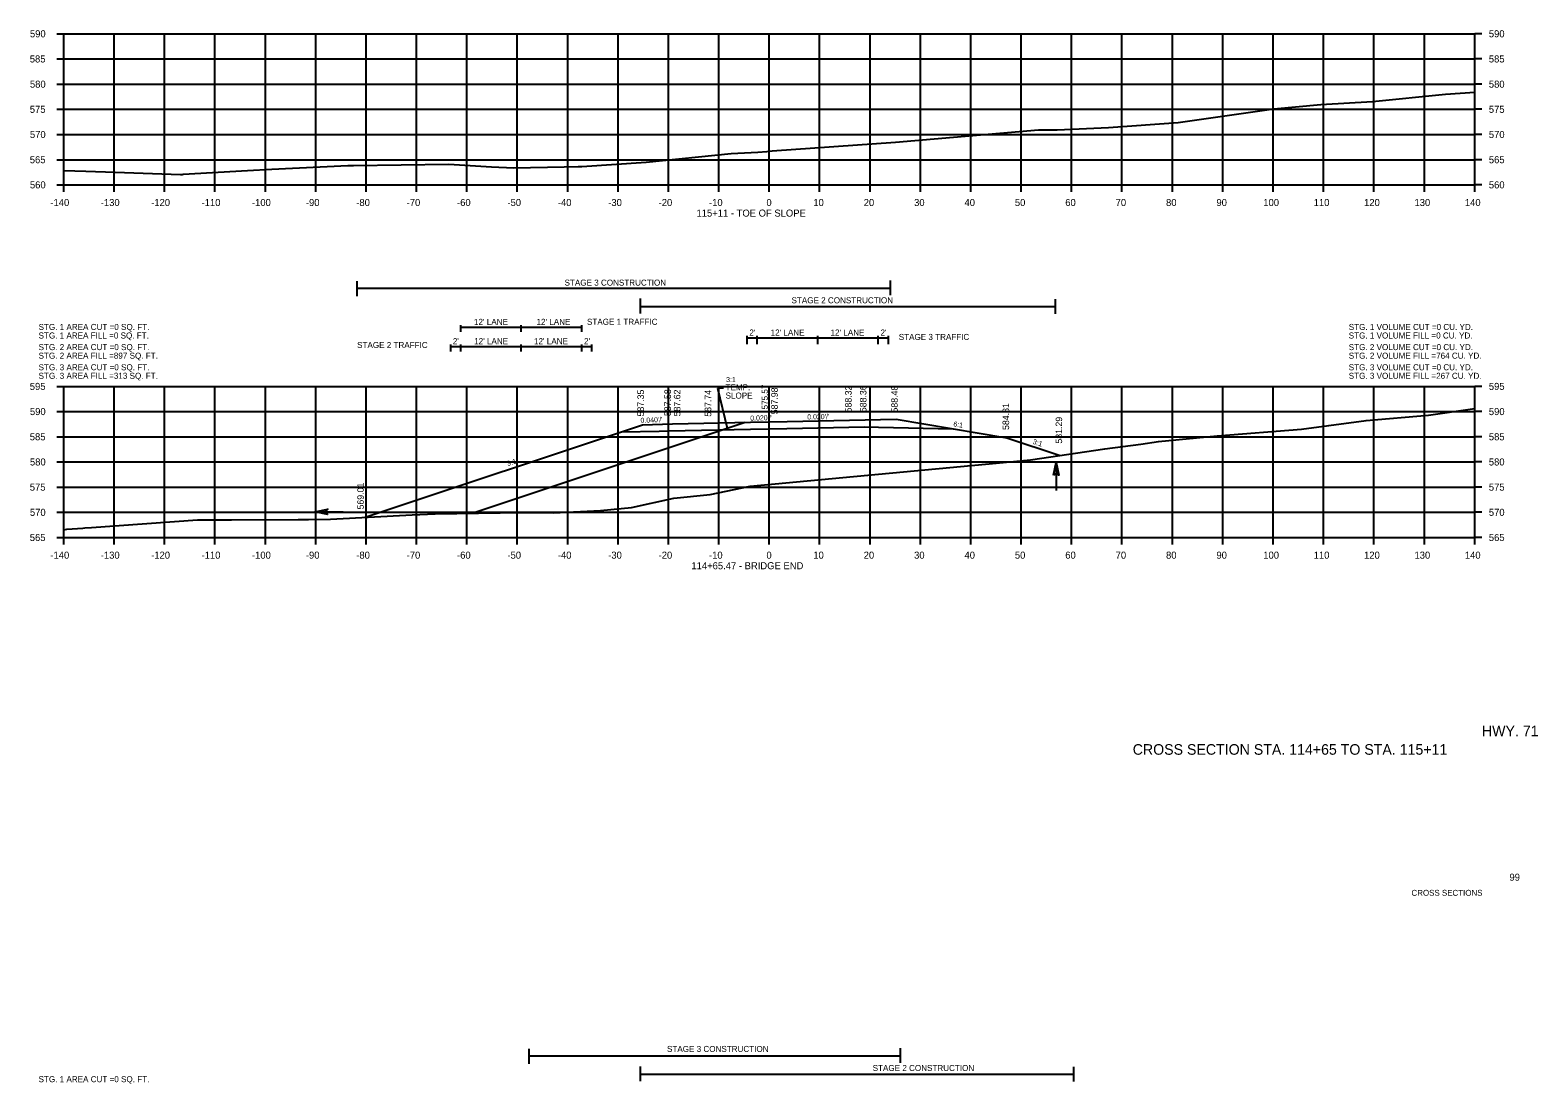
# Model space of a CAD drawing. Extents: x 642114 to 642416, y 286928 to 293347.
# Drawn here: x 642113.6 to 642412.8, y 289750.7 to 289959.9 of the extents above; entities that cross this region are included whole.
import ezdxf

# ---------------------------------------------------------------- set-up
doc = ezdxf.new("R2010")
doc.units = 0
for name, color, linetype in [('59', 7, 'Continuous'), ('Level 43', 7, 'Continuous'), ('Level 58', 7, 'Continuous'), ('R_Axis', 7, 'Continuous'), ('R_Axis Annot', 7, 'Continuous'), ('R_Border', 7, 'Continuous'), ('R_Border Notes', 7, 'Continuous'), ('R_Draft', 7, 'Continuous'), ('R_Exist Surface', 7, 'Continuous'), ('R_Exist Surface Annot', 7, 'Continuous'), ('R_Fin Surface', 7, 'Continuous'), ('R_Grid', 7, 'Continuous'), ('R_Xsect Elev', 7, 'Continuous'), ('R_Xsect Slope', 7, 'Continuous')]:
    doc.layers.add(name, color=color, linetype=linetype)

# ---------------------------------------------------------------- blocks, each defined once
blk = doc.blocks.new('FA')
at = {"layer": 'Level 43'}
blk.add_lwpolyline([(7.94, 0), (0, 0)], dxfattribs=at)
at = {"layer": 'Level 58'}
blk.add_lwpolyline([(4.34, 0.75), (7.94, 0), (4.34, -0.75), (4.94, 0)], close=True, dxfattribs=at)

msp = doc.modelspace()

# ---------------------------------------------------------------- linework, layer by layer
at = {"layer": 'R_Axis'}
for p, q in [((642118.84, 289959.14), (642120.24, 289959.14)), ((642120.24, 289929.14), (642120.24, 289959.14)), ((642400.24, 289929.14), (642400.24, 289959.14)), ((642401.64, 289959.14), (642400.24, 289959.14)), ((642118.84, 289954.14), (642120.24, 289954.14)), ((642401.64, 289954.14), (642400.24, 289954.14)), ((642118.84, 289949.14), (642120.24, 289949.14)), ((642401.64, 289949.14), (642400.24, 289949.14)), ((642118.84, 289944.14), (642120.24, 289944.14)), ((642401.64, 289944.14), (642400.24, 289944.14)), ((642118.84, 289939.14), (642120.24, 289939.14)), ((642401.64, 289939.14), (642400.24, 289939.14)), ((642118.84, 289934.14), (642120.24, 289934.14)), ((642401.64, 289934.14), (642400.24, 289934.14)), ((642118.84, 289929.14), (642120.24, 289929.14)), ((642120.24, 289929.14), (642400.24, 289929.14)), ((642120.24, 289927.74), (642120.24, 289929.14)), ((642130.24, 289927.74), (642130.24, 289929.14)), ((642140.24, 289927.74), (642140.24, 289929.14)), ((642150.24, 289927.74), (642150.24, 289929.14)), ((642160.24, 289927.74), (642160.24, 289929.14)), ((642170.24, 289927.74), (642170.24, 289929.14)), ((642180.24, 289927.74), (642180.24, 289929.14)), ((642190.24, 289927.74), (642190.24, 289929.14)), ((642200.24, 289927.74), (642200.24, 289929.14)), ((642210.24, 289927.74), (642210.24, 289929.14)), ((642220.24, 289927.74), (642220.24, 289929.14)), ((642230.24, 289927.74), (642230.24, 289929.14)), ((642240.24, 289927.74), (642240.24, 289929.14)), ((642250.24, 289927.74), (642250.24, 289929.14)), ((642260.24, 289927.74), (642260.24, 289929.14)), ((642270.24, 289927.74), (642270.24, 289929.14)), ((642280.24, 289927.74), (642280.24, 289929.14)), ((642290.24, 289927.74), (642290.24, 289929.14)), ((642300.24, 289927.74), (642300.24, 289929.14)), ((642310.24, 289927.74), (642310.24, 289929.14)), ((642320.24, 289927.74), (642320.24, 289929.14)), ((642330.24, 289927.74), (642330.24, 289929.14)), ((642340.24, 289927.74), (642340.24, 289929.14)), ((642350.24, 289927.74), (642350.24, 289929.14)), ((642360.24, 289927.74), (642360.24, 289929.14)), ((642370.24, 289927.74), (642370.24, 289929.14)), ((642380.24, 289927.74), (642380.24, 289929.14)), ((642390.24, 289927.74), (642390.24, 289929.14)), ((642400.24, 289927.74), (642400.24, 289929.14)), ((642401.64, 289929.14), (642400.24, 289929.14)), ((642118.84, 289889.14), (642120.24, 289889.14)), ((642120.24, 289859.14), (642120.24, 289889.14)), ((642400.24, 289859.14), (642400.24, 289889.14)), ((642401.64, 289889.14), (642400.24, 289889.14)), ((642118.84, 289884.14), (642120.24, 289884.14)), ((642401.64, 289884.14), (642400.24, 289884.14)), ((642118.84, 289879.14), (642120.24, 289879.14)), ((642401.64, 289879.14), (642400.24, 289879.14)), ((642118.84, 289874.14), (642120.24, 289874.14)), ((642401.64, 289874.14), (642400.24, 289874.14)), ((642118.84, 289869.14), (642120.24, 289869.14)), ((642401.64, 289869.14), (642400.24, 289869.14)), ((642118.84, 289864.14), (642120.24, 289864.14)), ((642401.64, 289864.14), (642400.24, 289864.14)), ((642118.84, 289859.14), (642120.24, 289859.14)), ((642120.24, 289859.14), (642400.24, 289859.14)), ((642120.24, 289857.74), (642120.24, 289859.14)), ((642130.24, 289857.74), (642130.24, 289859.14)), ((642140.24, 289857.74), (642140.24, 289859.14)), ((642150.24, 289857.74), (642150.24, 289859.14)), ((642160.24, 289857.74), (642160.24, 289859.14)), ((642170.24, 289857.74), (642170.24, 289859.14)), ((642180.24, 289857.74), (642180.24, 289859.14)), ((642190.24, 289857.74), (642190.24, 289859.14)), ((642200.24, 289857.74), (642200.24, 289859.14)), ((642210.24, 289857.74), (642210.24, 289859.14)), ((642220.24, 289857.74), (642220.24, 289859.14)), ((642230.24, 289857.74), (642230.24, 289859.14)), ((642240.24, 289857.74), (642240.24, 289859.14)), ((642250.24, 289857.74), (642250.24, 289859.14)), ((642260.24, 289857.74), (642260.24, 289859.14)), ((642270.24, 289857.74), (642270.24, 289859.14)), ((642280.24, 289857.74), (642280.24, 289859.14)), ((642290.24, 289857.74), (642290.24, 289859.14)), ((642300.24, 289857.74), (642300.24, 289859.14)), ((642310.24, 289857.74), (642310.24, 289859.14)), ((642320.24, 289857.74), (642320.24, 289859.14)), ((642330.24, 289857.74), (642330.24, 289859.14)), ((642340.24, 289857.74), (642340.24, 289859.14)), ((642350.24, 289857.74), (642350.24, 289859.14)), ((642360.24, 289857.74), (642360.24, 289859.14)), ((642370.24, 289857.74), (642370.24, 289859.14)), ((642380.24, 289857.74), (642380.24, 289859.14)), ((642390.24, 289857.74), (642390.24, 289859.14)), ((642400.24, 289857.74), (642400.24, 289859.14)), ((642401.64, 289859.14), (642400.24, 289859.14))]:
    msp.add_line(p, q, dxfattribs=at)
at = {"layer": 'R_Exist Surface'}
for points in [[(642120.24, 289932.01), (642124.59, 289931.86), (642130.41, 289931.67), (642143.38, 289931.22), (642143.71, 289931.23), (642143.92, 289931.25), (642156.69, 289931.99), (642161.54, 289932.27), (642176.58, 289932.97), (642177.51, 289932.99), (642177.71, 289932.98), (642196.67, 289933.22), (642205.09, 289932.74), (642209.52, 289932.51), (642219.55, 289932.73), (642222.32, 289932.78), (642222.94, 289932.77), (642223.06, 289932.8), (642235.81, 289933.67), (642252.65, 289935.38), (642257.97, 289935.64), (642259.75, 289935.78), (642260.82, 289935.87), (642285.28, 289937.62), (642313.64, 289940.07), (642317.36, 289940.06), (642327.59, 289940.53), (642341.41, 289941.51), (642360.37, 289944.23), (642369.67, 289945.09), (642379.93, 289945.7), (642394.43, 289947.17), (642400.24, 289947.55)], [(642230.94, 289880.12), (642238.42, 289880.27), (642240.33, 289880.3), (642256.49, 289880.63), (642260.24, 289880.7), (642263.76, 289880.77), (642279.13, 289881.08), (642281.92, 289881.02), (642296.76, 289880.73)]]:
    msp.add_lwpolyline(points, dxfattribs=at)
at = {"layer": 'R_Exist Surface Annot'}
msp.add_lwpolyline([(642120.24, 289860.69), (642120.86, 289860.77), (642124.01, 289860.99), (642124.41, 289861.03), (642125.75, 289861.13), (642146.78, 289862.68), (642153.5, 289862.62), (642166.78, 289862.74), (642168.81, 289862.73), (642173.18, 289862.79), (642189.36, 289863.63), (642193.92, 289863.86), (642211.16, 289864.11), (642217.39, 289864.04), (642226.74, 289864.53), (642232.91, 289865.09), (642241.32, 289866.98), (642248.52, 289867.7), (642256.43, 289869.35), (642305.26, 289873.91), (642312.07, 289874.53), (642326.83, 289876.76), (642333.96, 289877.69), (642337.46, 289878.17), (642349.11, 289879.32), (642365.87, 289880.64), (642371.3, 289881.37), (642378.71, 289882.36), (642391.07, 289883.41), (642400.24, 289884.77)], dxfattribs=at)
at = {"layer": 'R_Fin Surface'}
for points in [[(642180.02, 289863.15), (642235.07, 289881.49), (642241.07, 289881.73), (642256.49, 289882.04), (642260.24, 289882.12), (642263.77, 289882.19), (642285.41, 289882.62)], [(642285.41, 289882.62), (642307.41, 289878.95), (642317.99, 289875.42)]]:
    msp.add_lwpolyline(points, dxfattribs=at)
at = {"layer": 'R_Grid'}
for p, q in [((642120.24, 289959.14), (642400.24, 289959.14)), ((642120.24, 289929.14), (642120.24, 289959.14)), ((642130.24, 289929.14), (642130.24, 289959.14)), ((642140.24, 289929.14), (642140.24, 289959.14)), ((642150.24, 289929.14), (642150.24, 289959.14)), ((642160.24, 289929.14), (642160.24, 289959.14)), ((642170.24, 289929.14), (642170.24, 289959.14)), ((642180.24, 289929.14), (642180.24, 289959.14)), ((642190.24, 289929.14), (642190.24, 289959.14)), ((642200.24, 289929.14), (642200.24, 289959.14)), ((642210.24, 289929.14), (642210.24, 289959.14)), ((642220.24, 289929.14), (642220.24, 289959.14)), ((642230.24, 289929.14), (642230.24, 289959.14)), ((642240.24, 289929.14), (642240.24, 289959.14)), ((642250.24, 289929.14), (642250.24, 289959.14)), ((642260.24, 289929.14), (642260.24, 289959.14)), ((642270.24, 289929.14), (642270.24, 289959.14)), ((642280.24, 289929.14), (642280.24, 289959.14)), ((642290.24, 289929.14), (642290.24, 289959.14)), ((642300.24, 289929.14), (642300.24, 289959.14)), ((642310.24, 289929.14), (642310.24, 289959.14)), ((642320.24, 289929.14), (642320.24, 289959.14)), ((642330.24, 289929.14), (642330.24, 289959.14)), ((642340.24, 289929.14), (642340.24, 289959.14)), ((642350.24, 289929.14), (642350.24, 289959.14)), ((642360.24, 289929.14), (642360.24, 289959.14)), ((642370.24, 289929.14), (642370.24, 289959.14)), ((642380.24, 289929.14), (642380.24, 289959.14)), ((642390.24, 289929.14), (642390.24, 289959.14)), ((642400.24, 289929.14), (642400.24, 289959.14)), ((642120.24, 289954.14), (642400.24, 289954.14)), ((642120.24, 289949.14), (642400.24, 289949.14)), ((642120.24, 289944.14), (642400.24, 289944.14)), ((642120.24, 289939.14), (642400.24, 289939.14)), ((642120.24, 289934.14), (642400.24, 289934.14)), ((642120.24, 289929.14), (642400.24, 289929.14)), ((642120.24, 289889.14), (642400.24, 289889.14)), ((642120.24, 289859.14), (642120.24, 289889.14)), ((642130.24, 289859.14), (642130.24, 289889.14)), ((642140.24, 289859.14), (642140.24, 289889.14)), ((642150.24, 289859.14), (642150.24, 289889.14)), ((642160.24, 289859.14), (642160.24, 289889.14)), ((642170.24, 289859.14), (642170.24, 289889.14)), ((642180.24, 289859.14), (642180.24, 289889.14)), ((642190.24, 289859.14), (642190.24, 289889.14)), ((642200.24, 289859.14), (642200.24, 289889.14)), ((642210.24, 289859.14), (642210.24, 289889.14)), ((642220.24, 289859.14), (642220.24, 289889.14)), ((642230.24, 289859.14), (642230.24, 289889.14)), ((642240.24, 289859.14), (642240.24, 289889.14)), ((642250.24, 289859.14), (642250.24, 289889.14)), ((642260.24, 289859.14), (642260.24, 289889.14)), ((642270.24, 289859.14), (642270.24, 289889.14)), ((642280.24, 289859.14), (642280.24, 289889.14)), ((642290.24, 289859.14), (642290.24, 289889.14)), ((642300.24, 289859.14), (642300.24, 289889.14)), ((642310.24, 289859.14), (642310.24, 289889.14)), ((642320.24, 289859.14), (642320.24, 289889.14)), ((642330.24, 289859.14), (642330.24, 289889.14)), ((642340.24, 289859.14), (642340.24, 289889.14)), ((642350.24, 289859.14), (642350.24, 289889.14)), ((642360.24, 289859.14), (642360.24, 289889.14)), ((642370.24, 289859.14), (642370.24, 289889.14)), ((642380.24, 289859.14), (642380.24, 289889.14)), ((642390.24, 289859.14), (642390.24, 289889.14)), ((642400.24, 289859.14), (642400.24, 289889.14)), ((642120.24, 289884.14), (642400.24, 289884.14)), ((642120.24, 289879.14), (642400.24, 289879.14)), ((642120.24, 289874.14), (642400.24, 289874.14)), ((642120.24, 289869.14), (642400.24, 289869.14)), ((642120.24, 289864.14), (642400.24, 289864.14)), ((642120.24, 289859.14), (642400.24, 289859.14))]:
    msp.add_line(p, q, dxfattribs=at)
at = {"layer": 'R_Xsect Elev'}
for p, q in [((642178.45, 289907.08), (642178.45, 289910.01)), ((642284.28, 289907.22), (642284.28, 289910.15)), ((642178.45, 289908.66), (642284.28, 289908.66)), ((642234.67, 289903.63), (642234.67, 289906.56)), ((642317.06, 289903.54), (642317.06, 289906.47)), ((642234.67, 289905.01), (642317.06, 289905.01)), ((642199.03, 289899.99), (642199.03, 289901.31)), ((642199.03, 289900.89), (642223.03, 289900.89)), ((642211.03, 289899.99), (642211.03, 289901.31)), ((642223.03, 289899.99), (642223.03, 289901.31)), ((642197.03, 289896.04), (642197.03, 289897.47)), ((642197.03, 289897.06), (642225.03, 289897.06)), ((642199.03, 289896.04), (642199.03, 289897.47)), ((642211.03, 289896.04), (642211.03, 289897.47)), ((642223.03, 289896.04), (642223.03, 289897.47)), ((642225.03, 289896.04), (642225.03, 289897.47)), ((642255.87, 289897.53), (642255.87, 289899.19)), ((642255.87, 289898.77), (642283.87, 289898.77)), ((642257.87, 289897.53), (642257.87, 289899.19)), ((642269.87, 289897.53), (642269.87, 289899.19)), ((642281.87, 289897.53), (642281.87, 289899.19)), ((642283.87, 289897.53), (642283.87, 289899.19)), ((642201.28, 289863.96), (642255.46, 289882.02)), ((642212.57, 289754.69), (642212.57, 289757.61)), ((642286.31, 289754.83), (642286.31, 289757.75)), ((642212.57, 289756.26), (642286.31, 289756.26)), ((642234.67, 289751.24), (642234.67, 289754.16)), ((642320.71, 289751.14), (642320.71, 289754.07)), ((642234.67, 289752.62), (642320.71, 289752.62))]:
    msp.add_line(p, q, dxfattribs=at)
for points in [[(642251.17, 289888.82), (642249.95, 289888.82)], [(642249.95, 289888.82), (642251.91, 289880.87)]]:
    msp.add_lwpolyline(points, dxfattribs=at)

# ---------------------------------------------------------------- block references
at = {"layer": 'R_Xsect Elev', "xscale": 0.7, "yscale": 0.7}
for p, rotation in [((642317.2, 289868.46), 89.99999999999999), ((642175.65, 289864.23), 179.99999999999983)]:
    msp.add_blockref('FA', p, dxfattribs=dict(at, rotation=rotation))

# ---------------------------------------------------------------- texts
at = {"layer": '59'}
for s, p in [(' 587.35', (642235.38, 289882.69)), (' 587.58', (642240.73, 289882.77)), (' 587.62', (642242.61, 289882.71)), (' 587.74', (642248.73, 289882.64)), (' 587.98', (642261.94, 289883.12)), (' 588.32', (642276.58, 289883.5)), (' 588.36', (642279.53, 289883.54)), (' 588.48', (642285.74, 289883.47)), (' 584.81', (642307.84, 289880.01)), (' 581.29', (642318.36, 289877.3)), (' 569.01', (642179.78, 289864.22))]:
    msp.add_text(s, height=1.3, rotation=90, dxfattribs=at).set_placement(p)
at = {"layer": 'R_Axis Annot'}
for s, height, p in [('590', 1.4, (642113.52, 289958.44)), ('590', 1.4, (642403.04, 289958.44)), ('585', 1.4, (642113.49, 289953.44)), ('585', 1.4, (642403.04, 289953.44)), ('580', 1.4, (642113.52, 289948.44)), ('580', 1.4, (642403.04, 289948.44)), ('575', 1.4, (642113.49, 289943.44)), ('575', 1.4, (642403.04, 289943.44)), ('570', 1.4, (642113.52, 289938.44)), ('570', 1.4, (642403.04, 289938.44)), ('565', 1.4, (642113.49, 289933.44)), ('565', 1.4, (642403.04, 289933.44)), ('560', 1.4, (642113.52, 289928.44)), ('560', 1.4, (642403.04, 289928.44)), ('-140', 1.4, (642117.58, 289924.94)), ('-130', 1.4, (642127.58, 289924.94)), ('-120', 1.4, (642137.58, 289924.94)), ('-110', 1.4, (642147.58, 289924.94)), ('-100', 1.4, (642157.58, 289924.94)), ('-90', 1.4, (642168.28, 289924.94)), ('-80', 1.4, (642178.28, 289924.94)), ('-70', 1.4, (642188.28, 289924.94)), ('-60', 1.4, (642198.28, 289924.94)), ('-50', 1.4, (642208.28, 289924.94)), ('-40', 1.4, (642218.28, 289924.94)), ('-30', 1.4, (642228.28, 289924.94)), ('-20', 1.4, (642238.28, 289924.94)), ('115+11 - TOE OF SLOPE', 1.4, (642245.8, 289922.84)), ('-10', 1.4, (642248.28, 289924.94)), ('0', 1.4, (642259.68, 289924.94)), ('10', 1.4, (642268.98, 289924.94)), ('20', 1.4, (642278.98, 289924.94)), ('30', 1.4, (642288.98, 289924.94)), ('40', 1.4, (642298.98, 289924.94)), ('50', 1.4, (642308.98, 289924.94)), ('60', 1.4, (642318.98, 289924.94)), ('70', 1.4, (642328.98, 289924.94)), ('80', 1.4, (642338.98, 289924.94)), ('90', 1.4, (642348.98, 289924.94)), ('100', 1.4, (642358.28, 289924.94)), ('110', 1.4, (642368.28, 289924.94)), ('120', 1.4, (642378.28, 289924.94)), ('130', 1.4, (642388.28, 289924.94)), ('140', 1.4, (642398.28, 289924.94)), ('595', 1.4, (642113.49, 289888.44)), ('595', 1.4, (642403.04, 289888.44)), ('590', 1.4, (642113.52, 289883.44)), ('590', 1.4, (642403.04, 289883.44)), ('585', 1.4, (642113.49, 289878.44)), ('585', 1.4, (642403.04, 289878.44)), ('580', 1.4, (642113.52, 289873.44)), ('580', 1.4, (642403.04, 289873.44)), ('575', 1.4, (642113.49, 289868.44)), ('575', 1.4, (642403.04, 289868.44)), ('570', 1.4, (642113.52, 289863.44)), ('570', 1.4, (642403.04, 289863.44)), ('565', 1.4, (642113.49, 289858.44)), ('565', 1.4, (642403.04, 289858.44)), ('-140', 1.4, (642117.58, 289854.94)), ('-130', 1.4, (642127.58, 289854.94)), ('-120', 1.4, (642137.58, 289854.94)), ('-110', 1.4, (642147.58, 289854.94)), ('-100', 1.4, (642157.58, 289854.94)), ('-90', 1.4, (642168.28, 289854.94)), ('-80', 1.4, (642178.28, 289854.94)), ('-70', 1.4, (642188.28, 289854.94)), ('-60', 1.4, (642198.28, 289854.94)), ('-50', 1.4, (642208.28, 289854.94)), ('-40', 1.4, (642218.28, 289854.94)), ('-30', 1.4, (642228.28, 289854.94)), ('-20', 1.4, (642238.28, 289854.94)), ('-10', 1.4, (642248.28, 289854.94)), ('0', 1.4, (642259.68, 289854.94)), ('10', 1.4, (642268.98, 289854.94)), ('20', 1.4, (642278.98, 289854.94)), ('30', 1.4, (642288.98, 289854.94)), ('40', 1.4, (642298.98, 289854.94)), ('50', 1.4, (642308.98, 289854.94)), ('60', 1.4, (642318.98, 289854.94)), ('70', 1.4, (642328.98, 289854.94)), ('80', 1.4, (642338.98, 289854.94)), ('90', 1.4, (642348.98, 289854.94)), ('100', 1.4, (642358.28, 289854.94)), ('110', 1.4, (642368.28, 289854.94)), ('120', 1.4, (642378.28, 289854.94)), ('130', 1.4, (642388.28, 289854.94)), ('140', 1.4, (642398.28, 289854.94)), ('114+65.47 - BRIDGE END', 1.4, (642244.79, 289852.84)), ('HWY. 71', 2.1, (642401.67, 289819.69)), ('CROSS SECTION STA. 114+65 TO STA. 115+11', 2.1, (642332.37, 289816.02))]:
    msp.add_text(s, height=height, dxfattribs=at).set_placement(p)
at = {"layer": 'R_Border'}
msp.add_text('99', height=1.4, dxfattribs=at).set_placement((642407.13, 289791.01))
at = {"layer": 'R_Border Notes'}
msp.add_text('    CROSS SECTIONS    ', height=1.178, dxfattribs=at).set_placement((642385.94, 289788.02))
at = {"layer": 'R_Draft'}
for s, p in [('STG. 1 AREA CUT =0 SQ. FT.', (642115.24, 289900.34)), ('STG. 1 VOLUME CUT =0 CU. YD.', (642375.24, 289900.34)), ('STG. 1 AREA FILL =0 SQ. FT.', (642115.24, 289898.64)), ('STG. 2 AREA CUT =0 SQ. FT.', (642115.24, 289896.34)), ('STG. 1 VOLUME FILL =0 CU. YD.', (642375.24, 289898.64)), ('STG. 2 VOLUME CUT =0 CU. YD.', (642375.24, 289896.34)), ('STG. 2 AREA FILL =897 SQ. FT.', (642115.24, 289894.64)), ('STG. 2 VOLUME FILL =764 CU. YD.', (642375.24, 289894.64)), ('STG. 3 AREA CUT =0 SQ. FT.', (642115.24, 289892.34)), ('STG. 3 AREA FILL =313 SQ. FT.', (642115.24, 289890.64)), ('STG. 3 VOLUME CUT =0 CU. YD.', (642375.24, 289892.34)), ('STG. 3 VOLUME FILL =267 CU. YD.', (642375.24, 289890.64)), ('STG. 1 AREA CUT =0 SQ. FT.', (642115.24, 289751.02))]:
    msp.add_text(s, height=1.2, dxfattribs=at).set_placement(p)
at = {"layer": 'R_Xsect Elev'}
for s, p in [('STAGE 3 CONSTRUCTION', (642219.62, 289909.14)), ('STAGE 2 CONSTRUCTION', (642264.66, 289905.63)), ("12' LANE", (642201.65, 289901.35)), ("12' LANE", (642214.05, 289901.35)), ('STAGE 1 TRAFFIC', (642224.07, 289901.36)), ("2'", (642256.29, 289899.23)), ("12' LANE", (642260.51, 289899.23)), ("12' LANE", (642272.4, 289899.23)), ("2'", (642282.32, 289899.23)), ('STAGE 2 TRAFFIC', (642178.45, 289896.76)), ("2'", (642197.45, 289897.52)), ("12' LANE", (642201.68, 289897.52)), ("12' LANE", (642213.56, 289897.52)), ("2'", (642223.49, 289897.52)), ('STAGE 3 TRAFFIC', (642285.94, 289898.36)), ('TEMP.', (642251.57, 289888.35)), ('SLOPE', (642251.57, 289886.72)), ('STAGE 3 CONSTRUCTION', (642239.95, 289757.02)), ('STAGE 2 CONSTRUCTION', (642280.76, 289753.24))]:
    msp.add_text(s, height=1.2, dxfattribs=at).set_placement(p)
msp.add_text('575.57', height=1.2, rotation=90, dxfattribs=at).set_placement((642259.96, 289884.57))
at = {"layer": 'R_Xsect Slope'}
for s, rotation, p in [('3:1', 0.32, (642251.68, 289889.99)), ("0.040'/'", 2.2906, (642234.71, 289881.89)), ("0.020'/'", 1.1461, (642256.47, 289882.34)), ("0.020'/'", 1.1457, (642267.79, 289882.57)), ('6:1', 350.5413, (642296.72, 289881.23)), ('3:1', 341.5719, (642312.44, 289877.77)), ('3:1', 18.4334, (642208.36, 289873.3))]:
    msp.add_text(s, height=1, rotation=rotation, dxfattribs=at).set_placement(p)

doc.saveas('drawing.dxf')
